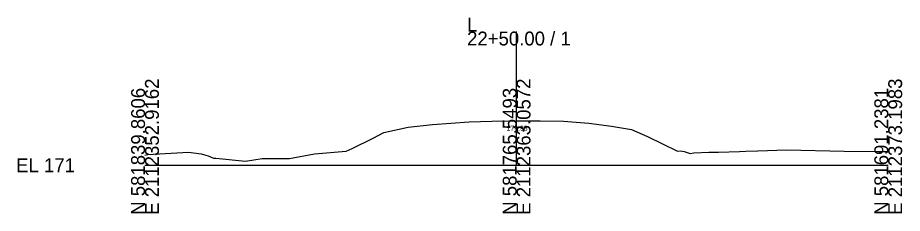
# Model space of a CAD drawing. Extents: x -486 to 1153, y -333 to 9539.
# Drawn here: x 974.3 to 1152.8, y 3490.3 to 3529.8 of the extents above; entities that cross this region are included whole.
import ezdxf

# ---------------------------------------------------------------- set-up
doc = ezdxf.new("R2010")
doc.units = 0
for name, color, linetype in [('Default', 7, 'Continuous'), ('Exist Cross Section Cell', 7, 'Continuous'), ('Exist XS Ground Line', 7, 'Continuous')]:
    doc.layers.add(name, color=color, linetype=linetype)

msp = doc.modelspace()

# ---------------------------------------------------------------- linework, layer by layer
at = {"layer": 'Exist Cross Section Cell'}
for p, q in [((1075, 3500), (1075, 3526.96)), ((1000, 3500), (1075, 3500)), ((1075, 3500), (1150, 3500))]:
    msp.add_line(p, q, dxfattribs=at)
at = {"layer": 'Exist XS Ground Line'}
for p, q in [((1053.14, 3507.69), (1058.04, 3508.24)), ((1058.04, 3508.24), (1065.41, 3508.78)), ((1065.41, 3508.78), (1070.01, 3508.87)), ((1070.01, 3508.87), (1074.9, 3508.99)), ((1074.9, 3508.99), (1079.75, 3508.94)), ((1079.75, 3508.94), (1084.43, 3508.88)), ((1084.43, 3508.88), (1089.55, 3508.48)), ((1089.55, 3508.48), (1094.17, 3507.86)), ((1046.02, 3505.48), (1048.22, 3506.61)), ((1048.22, 3506.61), (1053.14, 3507.69)), ((1094.17, 3507.86), (1098.2, 3507.22)), ((1098.2, 3507.22), (1101.39, 3505.82)), ((1041.78, 3503.39), (1046.02, 3505.48)), ((1101.39, 3505.82), (1107.45, 3502.83)), ((1040.58, 3502.81), (1041.78, 3503.39)), ((1107.45, 3502.83), (1108.12, 3502.91)), ((1108.12, 3502.91), (1108.81, 3502.8)), ((1120.01, 3502.76), (1121.25, 3502.81)), ((1121.25, 3502.81), (1123.69, 3502.92)), ((1123.69, 3502.92), (1129.46, 3503.12)), ((1129.46, 3503.12), (1141.13, 3502.85)), ((1141.13, 3502.85), (1148.18, 3502.78)), ((1000, 3502.05), (1000.6, 3502.18)), ((1000.6, 3502.18), (1008.75, 3502.63)), ((1008.75, 3502.63), (1011.31, 3502.27)), ((1011.31, 3502.27), (1012.73, 3501.92)), ((1012.73, 3501.92), (1013.83, 3501.44)), ((1013.83, 3501.44), (1014.3, 3501.4)), ((1014.3, 3501.4), (1020.25, 3500.84)), ((1020.25, 3500.84), (1023.62, 3501.37)), ((1023.62, 3501.37), (1029.13, 3501.36)), ((1029.13, 3501.36), (1034.2, 3502.28)), ((1034.2, 3502.28), (1040.58, 3502.81)), ((1108.81, 3502.8), (1110.02, 3502.35)), ((1110.02, 3502.35), (1110.78, 3502.5)), ((1110.78, 3502.5), (1113.79, 3502.64)), ((1113.79, 3502.64), (1115.74, 3502.62)), ((1115.74, 3502.62), (1120.01, 3502.76)), ((1148.18, 3502.78), (1150, 3502.78))]:
    msp.add_line(p, q, dxfattribs=at)

# ---------------------------------------------------------------- texts
at = {"layer": 'Default'}
for s, height, p in [('179.98', 1, (1072.98, 3506.98)), ('-', 0.0001, (1000, 3500))]:
    msp.add_text(s, height=height, dxfattribs=at).set_placement(p)
at = {"layer": 'Exist Cross Section Cell'}
for s, p in [('L', (1065, 3526.96)), ('22+50.00 / 1', (1065, 3524.16)), ('EL 171', (974, 3498.6))]:
    msp.add_text(s, height=2.8, dxfattribs=at).set_placement(p)
for s, p in [('E 2112352.9162', (1002.8, 3490)), ('E 2112363.0572', (1077.8, 3490)), ('E 2112373.1983', (1152.8, 3490)), ('N 581839.8606', (1000, 3490)), ('N 581765.5493', (1075, 3490)), ('N 581691.2381', (1150, 3490))]:
    msp.add_text(s, height=2.8, rotation=90, dxfattribs=at).set_placement(p)

doc.saveas('drawing.dxf')
